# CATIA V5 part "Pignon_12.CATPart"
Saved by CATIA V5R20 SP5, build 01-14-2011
Part number: Pignon_12
Bounding box of the stored display mesh (mm): x -2 to 6, y 1.199 to 7, z 0.102 to 6.093
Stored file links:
  F:\Catia_finish\Pignon_12.CATPart
  D:\Ecole\Ifma\2A\S3\CFAO\ThinkMotion\Catia\pignon.CATPart
  F:\Catia_finish\ASS_compresseur.CATProduct
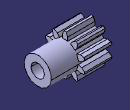
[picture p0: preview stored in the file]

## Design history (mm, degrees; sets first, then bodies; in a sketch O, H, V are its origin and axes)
Solid1: solid without history
Line1: linked copy from another document
Set1
  Point1: linked copy from another document
  Point2: linked copy from another document
Body1 "1" (main body)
